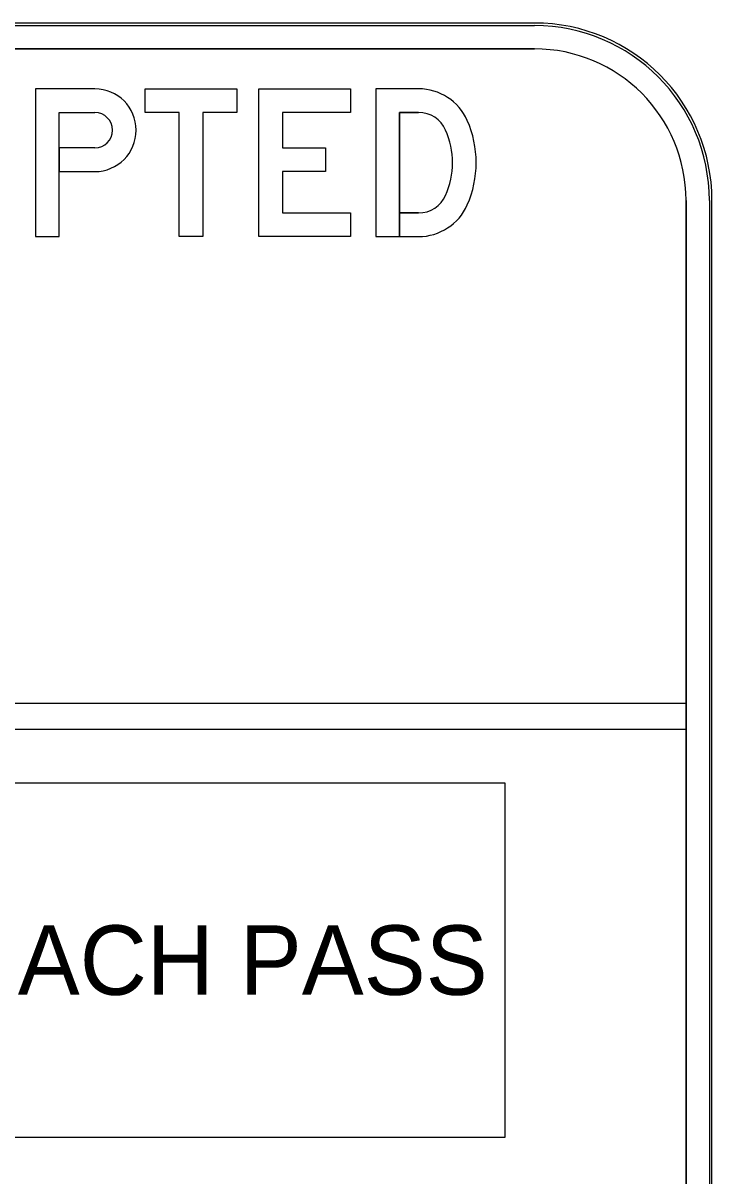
# Model space of a CAD drawing. Extents: x 17890628 to 17891459, y 17897314 to 17897992.
# Drawn here: x 17890748.88 to 17890752.76, y 17897485.83 to 17897492.33 of the extents above; entities that cross this region are included whole.
import ezdxf

# ---------------------------------------------------------------- set-up
doc = ezdxf.new("R2010")
doc.units = 0
for name, color, linetype in [('GSColorFill', 7, 'Continuous'), ('GSOutline', 7, 'Continuous'), ('XSCell', 7, 'Continuous')]:
    doc.layers.add(name, color=color, linetype=linetype)

msp = doc.modelspace()

# ---------------------------------------------------------------- linework, layer by layer
at = {"layer": 'GSColorFill'}
for p, q in [((17890751.7629, 17897492.3302), (17890739.2629, 17897492.3302)), ((17890751.7629, 17897492.3302), (17890739.2629, 17897492.3302)), ((17890751.7629, 17897492.3302), (17890739.2629, 17897492.3302)), ((17890739.2629, 17897492.3156), (17890751.7629, 17897492.3156)), ((17890739.2629, 17897492.1844), (17890751.7629, 17897492.1844)), ((17890751.1096, 17897491.9593), (17890750.8677, 17897491.9593)), ((17890749.0843, 17897491.8259), (17890749.2843, 17897491.8259)), ((17890749.0843, 17897491.8259), (17890749.2843, 17897491.8259)), ((17890751.1096, 17897491.8259), (17890751.001, 17897491.8259)), ((17890749.0843, 17897491.4926), (17890749.2843, 17897491.4926)), ((17890752.6171, 17897491.3302), (17890752.6171, 17897481.3302)), ((17890752.7483, 17897491.3302), (17890752.7483, 17897481.3302)), ((17890752.7629, 17897481.3302), (17890752.7629, 17897491.3302)), ((17890752.7629, 17897481.3302), (17890752.7629, 17897491.3302)), ((17890752.7629, 17897481.3302), (17890752.7629, 17897491.3302)), ((17890751.1096, 17897491.2593), (17890751.001, 17897491.2593)), ((17890751.1096, 17897491.2593), (17890751.001, 17897491.2593)), ((17890752.6171, 17897488.4931), (17890738.4088, 17897488.4931)), ((17890752.6171, 17897488.3473), (17890752.6171, 17897488.4931)), ((17890738.4088, 17897488.3473), (17890752.6171, 17897488.3473))]:
    msp.add_line(p, q, dxfattribs=at)
for points in [[(17890749.2843, 17897491.9593), (17890748.951, 17897491.9593), (17890748.951, 17897491.1259), (17890749.0843, 17897491.1259), (17890749.0843, 17897491.4926)], [(17890749.2843, 17897491.9593), (17890748.951, 17897491.9593), (17890748.951, 17897491.1259), (17890749.0843, 17897491.1259), (17890749.0843, 17897491.8259)], [(17890749.2843, 17897491.9593), (17890748.951, 17897491.9593), (17890748.951, 17897491.1259), (17890749.0843, 17897491.1259), (17890749.0843, 17897491.8259)], [(17890751.1096, 17897491.9593), (17890750.8677, 17897491.9593), (17890750.8677, 17897491.1259), (17890751.001, 17897491.1259), (17890751.001, 17897491.8259), (17890751.1096, 17897491.8259)], [(17890751.1096, 17897491.9593), (17890750.8677, 17897491.9593), (17890750.8677, 17897491.1259), (17890751.001, 17897491.1259), (17890751.001, 17897491.8259), (17890751.1096, 17897491.8259)], [(17890750.8677, 17897491.9593), (17890750.8677, 17897491.1259), (17890751.1096, 17897491.1259)], [(17890749.2843, 17897491.6259), (17890749.0843, 17897491.6259), (17890749.0843, 17897491.8259), (17890749.2843, 17897491.8259)], [(17890751.001, 17897491.8259), (17890751.001, 17897491.2593), (17890751.1096, 17897491.2593)], [(17890749.2843, 17897491.6259), (17890749.0844, 17897491.6259), (17890749.0844, 17897491.4926), (17890749.2843, 17897491.4926)], [(17890749.2843, 17897491.6259), (17890749.0844, 17897491.6259), (17890749.0844, 17897491.4926), (17890749.2843, 17897491.4926)], [(17890751.001, 17897491.2593), (17890751.001, 17897491.1259), (17890751.1096, 17897491.1259)], [(17890751.001, 17897491.2593), (17890751.001, 17897491.1259), (17890751.1096, 17897491.1259)]]:
    msp.add_lwpolyline(points, dxfattribs=at)
for points in [[(17890750.0843, 17897491.9593), (17890750.0843, 17897491.8259), (17890749.8927, 17897491.8259), (17890749.8927, 17897491.1259), (17890749.7593, 17897491.1259), (17890749.7593, 17897491.8259), (17890749.5677, 17897491.8259), (17890749.5677, 17897491.9593)], [(17890750.0843, 17897491.9593), (17890750.0843, 17897491.8259), (17890749.8927, 17897491.8259), (17890749.8927, 17897491.1259), (17890749.7593, 17897491.1259), (17890749.7593, 17897491.8259), (17890749.5677, 17897491.8259), (17890749.5677, 17897491.9593)], [(17890750.0843, 17897491.9593), (17890750.0843, 17897491.8259), (17890749.8927, 17897491.8259), (17890749.8927, 17897491.1259), (17890749.7593, 17897491.1259), (17890749.7593, 17897491.8259), (17890749.5677, 17897491.8259), (17890749.5677, 17897491.9593)], [(17890750.726, 17897491.8259), (17890750.3427, 17897491.8259), (17890750.3427, 17897491.6259), (17890750.585, 17897491.6259), (17890750.585, 17897491.4926), (17890750.3427, 17897491.4926), (17890750.3427, 17897491.2593), (17890750.726, 17897491.2593), (17890750.726, 17897491.1259), (17890750.2093, 17897491.1259), (17890750.2093, 17897491.9593), (17890750.726, 17897491.9593)], [(17890750.726, 17897491.8259), (17890750.3427, 17897491.8259), (17890750.3427, 17897491.6259), (17890750.585, 17897491.6259), (17890750.585, 17897491.4926), (17890750.3427, 17897491.4926), (17890750.3427, 17897491.2593), (17890750.726, 17897491.2593), (17890750.726, 17897491.1259), (17890750.2093, 17897491.1259), (17890750.2093, 17897491.9593), (17890750.726, 17897491.9593)], [(17890750.726, 17897491.8259), (17890750.3427, 17897491.8259), (17890750.3427, 17897491.6259), (17890750.585, 17897491.6259), (17890750.585, 17897491.4926), (17890750.3427, 17897491.4926), (17890750.3427, 17897491.2593), (17890750.726, 17897491.2593), (17890750.726, 17897491.1259), (17890750.2093, 17897491.1259), (17890750.2093, 17897491.9593), (17890750.726, 17897491.9593)], [(17890746.0129, 17897488.0456), (17890751.5959, 17897488.0456), (17890751.5959, 17897486.0456), (17890746.0129, 17897486.0456)]]:
    msp.add_lwpolyline(points, close=True, dxfattribs=at)
for radius in [1, 1, 1, 0.9854, 0.8542]:
    msp.add_arc((17890751.7629, 17897491.3302), radius, 0, 90, dxfattribs=at)
for centre, major_axis, start_param, end_param in [((17890749.2843, 17897491.7259), (0, 0.2333), 3.141593, 6.283185), ((17890749.2843, 17897491.7259), (0, 0.2333), 3.141593, 6.283185), ((17890749.2843, 17897491.7259), (0, 0.2333), 3.141593, 6.283185), ((17890751.1096, 17897491.6593), (0, 0.3), 5.13024, 6.283185), ((17890751.1096, 17897491.6593), (0, 0.3), 5.13024, 6.283185), ((17890751.1096, 17897491.6593), (0, 0.3), 5.13024, 6.283185), ((17890749.2843, 17897491.7259), (0, 0.1), 3.141593, 6.283185), ((17890749.2843, 17897491.7259), (0, 0.1), 3.141593, 6.283185), ((17890749.2843, 17897491.7259), (0, 0.1), 3.141593, 6.283185), ((17890751.1096, 17897491.6593), (0, 0.1667), 5.13024, 6.283185), ((17890751.1096, 17897491.6593), (0, 0.1667), 5.13024, 6.283185), ((17890751.1096, 17897491.6593), (0, 0.1667), 5.13024, 6.283185), ((17890750.8468, 17897491.5426), (0, 0.5875), 4.294538, 5.13024), ((17890750.8468, 17897491.5426), (0, 0.5875), 4.294538, 5.13024), ((17890750.8468, 17897491.5426), (0, 0.5875), 4.294538, 5.13024), ((17890750.8468, 17897491.5426), (0, 0.4542), 4.294538, 5.13024), ((17890750.8468, 17897491.5426), (0, 0.4542), 4.294538, 5.13024), ((17890750.8468, 17897491.5426), (0, 0.4542), 4.294538, 5.13024), ((17890751.1096, 17897491.4259), (0, 0.1667), 3.141593, 4.294538), ((17890751.1096, 17897491.4259), (0, 0.1667), 3.141593, 4.294538), ((17890751.1096, 17897491.4259), (0, 0.1667), 3.141593, 4.294538), ((17890751.1096, 17897491.4259), (0, 0.3), 3.141593, 4.294538), ((17890751.1096, 17897491.4259), (0, 0.3), 3.141593, 4.294538), ((17890751.1096, 17897491.4259), (0, 0.3), 3.141593, 4.294538)]:
    msp.add_ellipse(centre, major_axis=major_axis, ratio=0.999997, start_param=start_param, end_param=end_param, dxfattribs=at)
at = {"layer": 'GSOutline'}
for p, q in [((17890751.7629, 17897492.3302), (17890739.2629, 17897492.3302)), ((17890739.2629, 17897492.1844), (17890751.7629, 17897492.1844)), ((17890752.6171, 17897491.3302), (17890752.6171, 17897481.3302)), ((17890752.7629, 17897481.3302), (17890752.7629, 17897491.3302)), ((17890752.6171, 17897488.4931), (17890738.4088, 17897488.4931)), ((17890752.6171, 17897488.3473), (17890752.6171, 17897488.4931)), ((17890738.4088, 17897488.3473), (17890752.6171, 17897488.3473))]:
    msp.add_line(p, q, dxfattribs=at)
for radius in [1, 0.8542]:
    msp.add_arc((17890751.7629, 17897491.3302), radius, 0, 90, dxfattribs=at)
at = {"layer": 'XSCell'}
for p, q in [((17890751.7629, 17897492.3302), (17890739.2629, 17897492.3302)), ((17890751.7629, 17897492.1844), (17890739.2629, 17897492.1844)), ((17890752.6171, 17897481.3302), (17890752.6171, 17897491.3302)), ((17890752.7629, 17897481.3302), (17890752.7629, 17897491.3302)), ((17890752.6171, 17897488.4931), (17890738.4088, 17897488.4931)), ((17890752.6171, 17897488.3473), (17890752.6171, 17897488.4931)), ((17890738.4088, 17897488.3473), (17890752.6171, 17897488.3473))]:
    msp.add_line(p, q, dxfattribs=at)
for radius in [1, 0.8542]:
    msp.add_arc((17890751.7629, 17897491.3302), radius, 0, 90, dxfattribs=at)

# ---------------------------------------------------------------- texts
at = {"layer": 'GSColorFill'}
msp.add_text('PEACH PASS', height=0.39168, dxfattribs=at).set_placement((17890748.1516, 17897486.8497))

doc.saveas('drawing.dxf')
